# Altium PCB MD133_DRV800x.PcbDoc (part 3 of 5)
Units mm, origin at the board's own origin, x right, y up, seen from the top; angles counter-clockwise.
Board outline 152.66 x 101.89 mm, 4 copper layers (Top Layer, Mid-Layer 1, Mid-Layer 2, Bottom Layer), stack 2.355 mm thick; 306 components, 166 nets, 1010 pads, 1623 vias.
Unrouted connection lines stored in the file: 4.
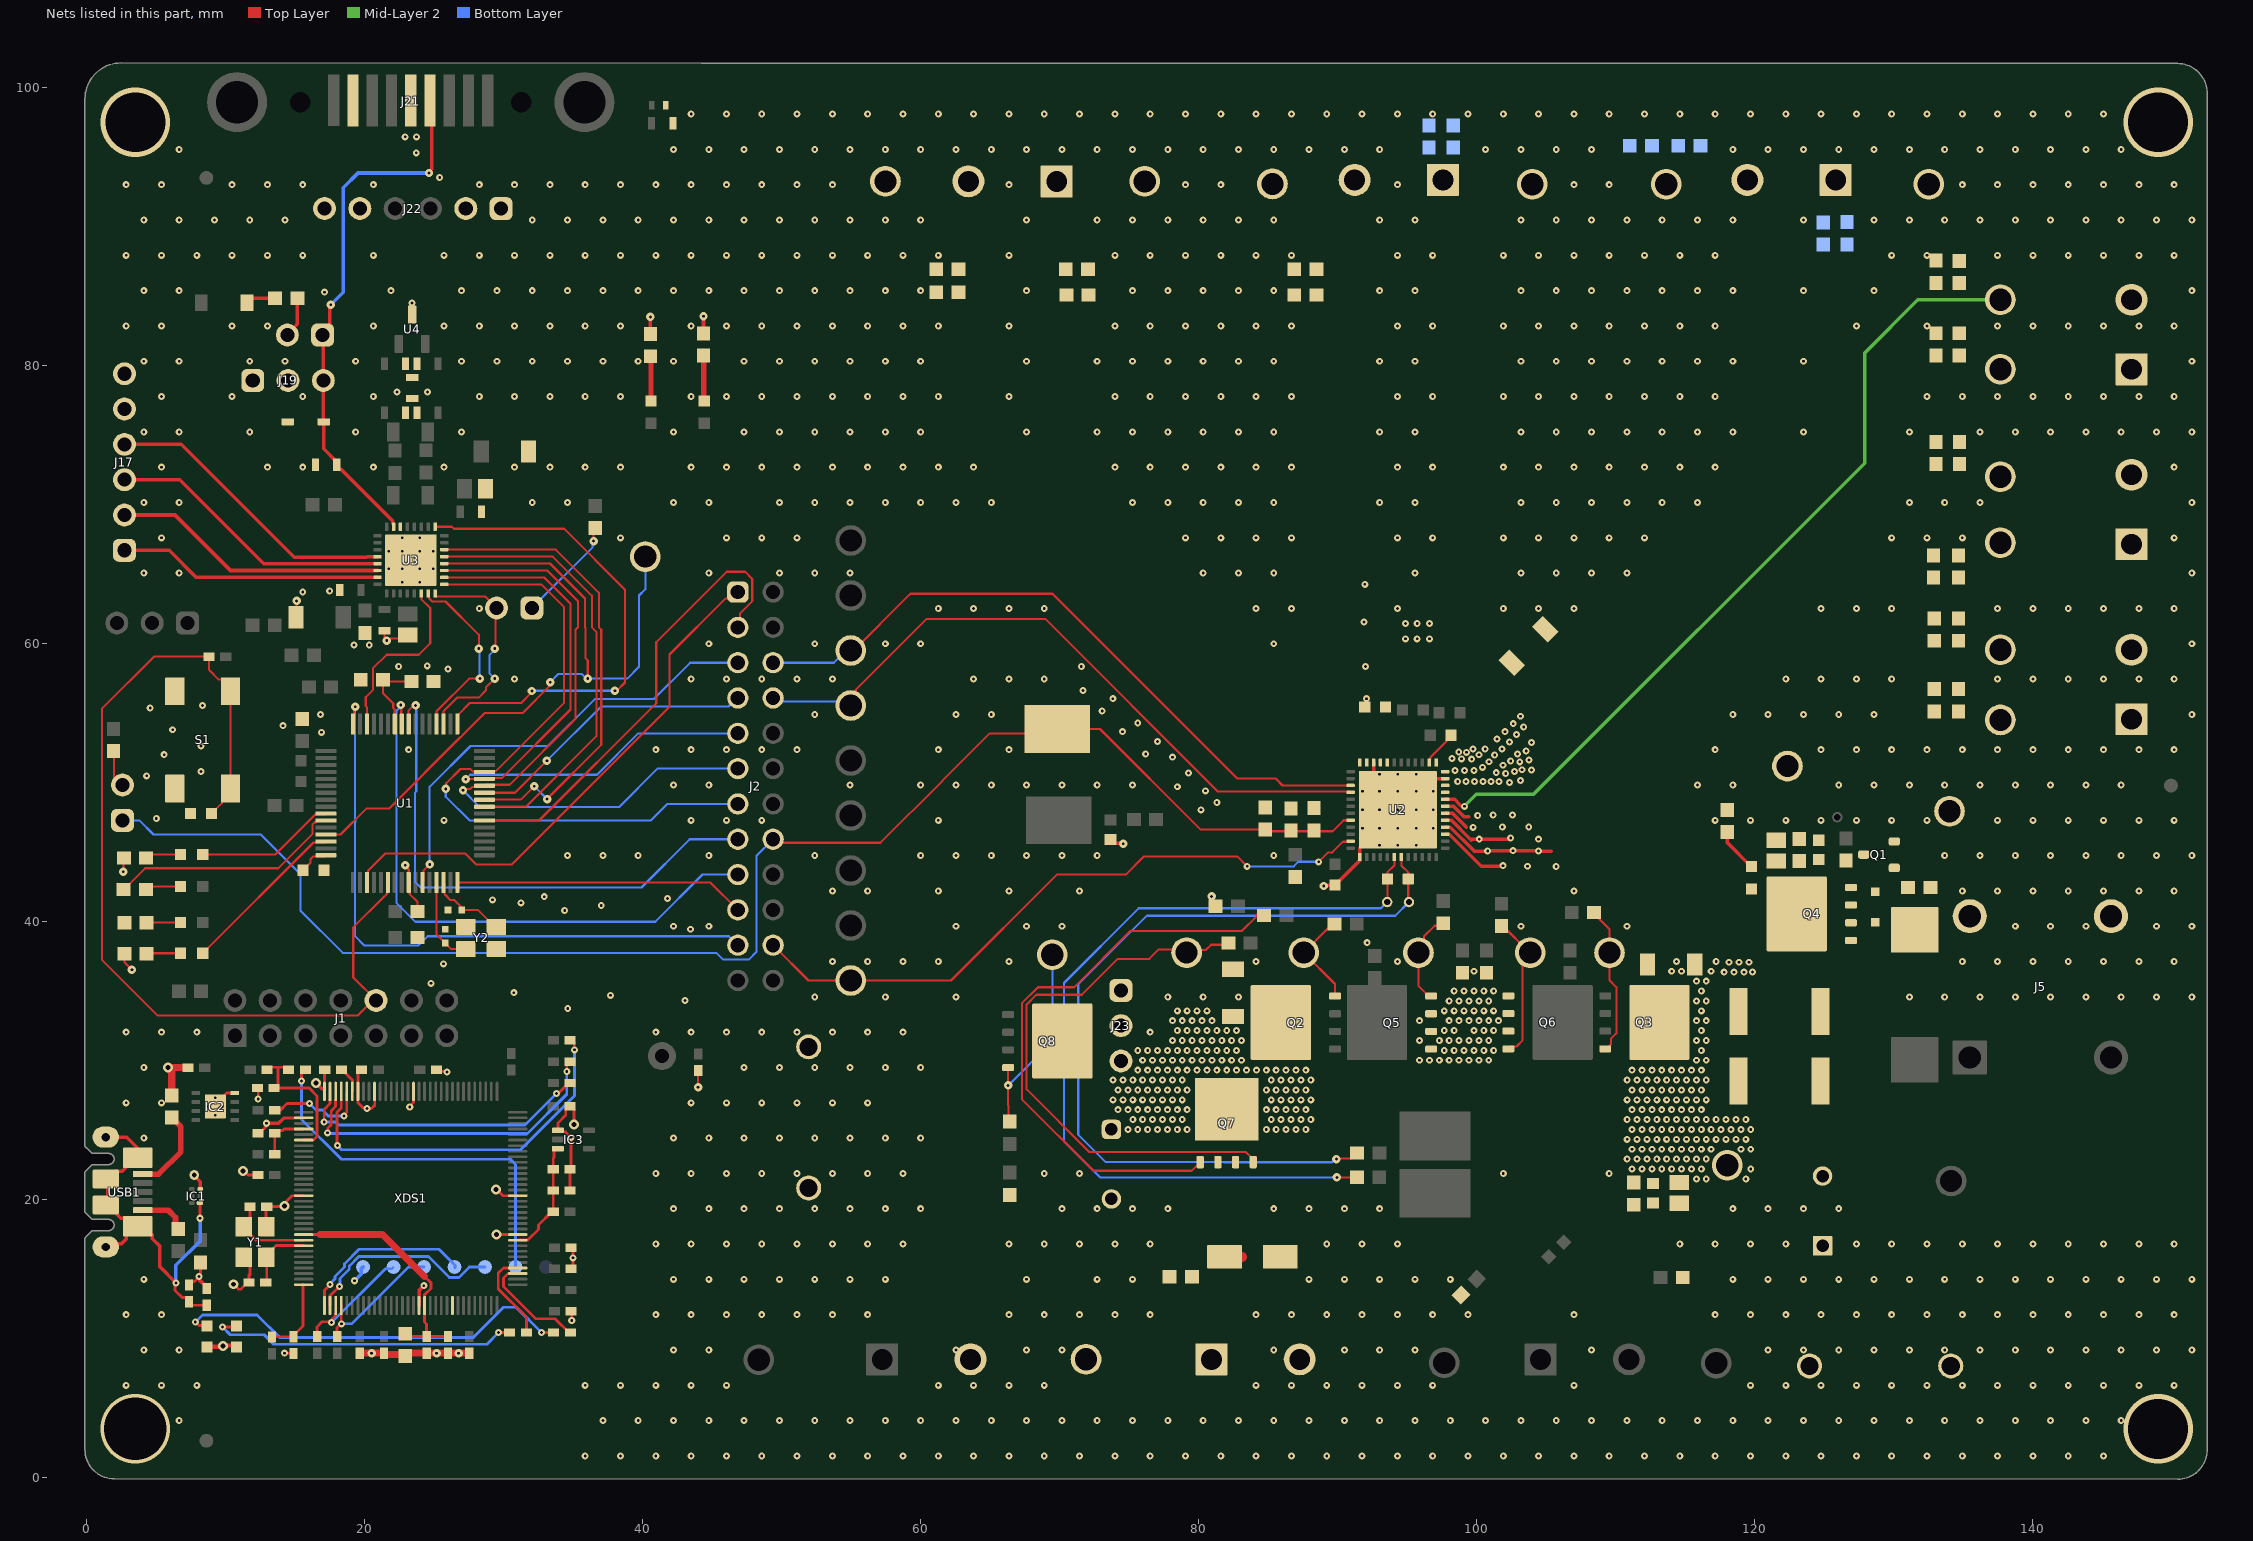
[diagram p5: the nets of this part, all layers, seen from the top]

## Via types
v1: diameter 0.5, hole 0.2, Top Layer to Bottom Layer, tented both sides, 1483 vias
v2: diameter 0.61, hole 0.2, Top Layer to Bottom Layer, tented both sides, 58 vias
v3: diameter 0.508, hole 0.203, Top Layer to Bottom Layer, tented both sides, 46 vias
v4: diameter 0.5, hole 0.2, Top Layer to Bottom Layer, 16 vias
v5: diameter 0.711, hole 0.356, Top Layer to Bottom Layer, tented both sides, 10 vias
v6: diameter 0.61, hole 0.203, Top Layer to Bottom Layer, tented both sides, 5 vias
v7: diameter 5, hole 4.3, Top Layer to Bottom Layer, 3 vias
v8: diameter 5, hole 4.5, Top Layer to Bottom Layer, 1 vias
v9: diameter 0.864, hole 0.406, Top Layer to Bottom Layer, tented both sides, 1 vias

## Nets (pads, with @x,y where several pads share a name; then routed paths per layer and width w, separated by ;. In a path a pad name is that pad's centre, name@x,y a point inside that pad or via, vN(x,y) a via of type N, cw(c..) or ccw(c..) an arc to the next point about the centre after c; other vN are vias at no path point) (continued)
GND: C1.2 C2.2 C3.2 C4.2 C5.2 C6.2 C7.2 C8.2 C9.2 C10.2 C11.2 C12.2 C13.2 C14.2 C15.2 C16.2 C17.2 C18.2 C19.2 C20.2 C21.2 C22.2 C23.2 C24.2 C25.1 C26.1 C28.1 C29.1 C30.1 C31.2 C32.1 C33.2 C34.2 C35.2 C36.2 C37.2 C38.2 C39.1 C41.1 C42.1 C43.1 C44.2 C45.1 C49.1 C50.1 C51.1 C52.1 C53.1 C54.1 C55.1 C56.1 C57.1 C58.1 C59.1 C60.1 C61.1 C63.2 C64.1 C65.1 C66.1 C67.2 C68.2 C69.2 C70.2 C71.1 C72.1 C73.1 C74.2 C75.2 C76.2 C77.2 C78.2 C79.2 C80.2 C81.2 C82.1 C83.2 C84.1 C85.2 C86.2 C87.1 C88.1 C89.1 C90.1 C91.1 C92.1 D9.2 D11.2 IC1.3 IC2.4 IC2.9 IC3.1 J5.2 J9.2 J16.2 J17.5 J17.6 J19.1 J19.2 J21.3 J21.6 J22.1 J22.2 J22.5 J22.6 LED1.2 LED2.2 Q5.1 Q5.2 Q5.3 Q6.1 Q6.2 Q6.3 R2.2 R3.1 R6.1 R15.1 R23.1 R27.1 R28.1 R29.1 R30.1 R33.1 R41.1 R42.1 R44.1 R57.1 R62.1 R63.1 R72.1 R77.1 S1.3 S1.4 SH1.1 SH1.2 SH2.1 SH2.2 TP1.1 TP25.1 TP26.1 U1.41 U2.10 U2.25 U2.47 U2.49 U3.30 U3.33 U4.3 XDS1.10 XDS1.17 XDS1.48 XDS1.55 XDS1.58 XDS1.64 XDS1.66 XDS1.80 XDS1.114 Y1.2 Y1.4 Y2.2 Y2.4 | length 94.7
  Top Layer w0.152: v2(2.634,43.577) 2.634,44.538 R29.1@2.677,44.582 ; R30.1@2.715,37.689 2.715,37.069 v2(3.25,36.534) ; C76.2@15.058,61.893 15.1,61.935 v2(15.1,63.066) ; C77.2@21.426,60.919 21.426,60.374 v2(21.59,60.21) 21.714,60.21 21.871,60.368 22.858,60.368 C75.2@23.108,60.618 ; v2(22.907,44.05) 22.907,44.004 23.162,43.749 U1.41@23.162,42.814 23.236,42.74 23.236,41.976 23.795,41.417 C24.2@23.795,40.714 ; U4.3@23.406,83.862 v1(23.406,84.497) ; C83.2@28.393,70.842 C83.2@28.681,71.131 C83.2@28.681,71.281 ; C78.2@31.304,73.086 31.778,73.559 C78.2@31.778,73.81 ; v2(43.979,28.086) R23.1@43.979,29.286 ; C45.1@91.938,55.421 92.052,55.535 v1(92.052,56.033) ; C45.1@91.988,55.421 C45.1@92.277,55.132
  Top Layer w0.203: R6.1@7.555,13.603 7.356,13.802 R6.1@7.356,13.848 R6.1@7.356,13.886 ; R6.1@7.645,14.146 7.555,14.146 7.356,13.948 R6.1@7.356,13.886 ; v3@8.027,14.529 8.182,14.683 C1.2@8.182,15.488 ; v3(8.089,14.467) 7.706,14.085 7.555,14.085 R6.1@7.356,13.886 ; v4(9.253,27.321) 9.753,27.321 9.902,27.469 9.902,27.524 10.048,27.671 IC2.4@10.653,27.671 ; v5(10.564,13.908) 10.572,13.908 10.924,13.556 11.093,13.556 11.578,14.042 C19.2@11.679,14.042 11.679,14.592 ; v5(11.242,22.062) 11.335,22.062 11.624,21.772 C5.2@12.329,21.772 ; Y1.4@11.395,16.19 11.395,15.801 11.753,15.443 11.753,14.592 ; C12.2@12.273,28.03 12.335,27.968 v3(12.335,27.243) ; C22.2@12.329,24.78 12.429,24.78 12.886,25.237 12.886,25.432 v3(12.944,25.491) v3@12.886,25.549 ; Y1.2@12.907,18.089 12.907,19.442 C18.2@12.953,19.488 12.974,19.509 14.203,19.509 v5(14.225,19.53) 14.322,19.627 14.322,19.832 14.77,20.28 XDS1.80@15.607,20.28 ; 14.163,25.872 14.172,25.88 XDS1.66@15.607,25.88 ; v3(14.225,8.949) 14.866,8.949 C11.2@14.88,8.935 ; XDS1.64@17.107,27.78 XDS1.64@17.107,27.978 ; XDS1.64@17.107,28.379 R15.1@17.107,29.323 ; C7.2@19.742,29.482 19.717,29.482 19.519,29.283 19.519,27.169 19.521,27.167 19.521,26.966 19.879,26.607 20.112,26.607 v3(20.17,26.549) 20.171,26.55 20.481,26.55 20.719,26.788 20.719,27.172 XDS1.55@20.709,27.182 ; v3(23.236,26.652) 23.236,26.707 23.507,26.978 XDS1.48@23.507,27.78 ; C6.2@25.157,29.336 25.261,29.232 25.865,29.232 v3(25.924,29.174) ; v5@29.48,17.489 XDS1.10@31.018,17.489 ; v5@29.51,20.715 29.945,20.28 XDS1.17@31.007,20.28 ; C20.2@34.756,20.651 C21.2@34.756,22.174 34.844,22.262 v3(34.844,24.479) 34.449,24.874 33.99,24.874 IC3.1@33.892,24.972 33.892,25.508 34.458,26.074 34.458,26.511 34.656,26.709 C14.2@34.756,26.709 34.844,26.709 35.042,26.511 v5(35.042,25.414) ; R3.1@34.844,11.976 34.89,11.931 v3(34.89,11.292) ; C8.2@34.844,15.022 34.991,15.17 v3(34.991,15.813) 34.991,16.398 C13.2@34.844,16.545
  Top Layer w0.254: v5(7.737,21.757) 7.737,21.72 8.164,21.293 IC1.3@8.164,20.758 ; v3(8.089,14.467) 8.118,14.438 8.118,14.212 8.626,13.703 C2.2@8.626,13.603 ; v3(12.944,25.491) 13.8,25.491 14.172,25.863 ; v5(16.5,28.386) 16.908,27.978 XDS1.64@17.08,27.978 ; XDS1.114@23.907,12.38 23.907,13.461 24.247,13.801 v3(24.247,13.807) ; v5(29.429,20.715) v5@29.51,20.715 ; v2(40.553,83.492) 40.553,82.273 R63.1@40.566,82.261 ; R62.1@44.368,82.311 v2(44.368,83.542) ; C63.2@73.636,45.9 73.909,45.627 74.536,45.627 v2(74.562,45.601) ; v2(88.978,42.557) 89.044,42.623 C43.1@89.798,42.623 91.563,44.388 91.563,44.637 U2.25@91.565,44.639 91.565,45.289 v1(94.315,48.039) ; U2.10@92.565,51.439 92.565,50.712 92.747,50.433 v1(94.315,48.039) ; U2.47@97.715,50.289 96.988,50.289 95.749,49.246 v1(94.315,48.039)
  Top Layer w0.305: LED1.2@8.753,9.349 8.81,9.406 9.738,9.406 v5(9.795,9.463) 9.838,9.506 10.742,9.506 LED2.2@10.785,9.549
  Top Layer w0.508: R2.2@6.117,27.496 6.117,29.189 5.858,29.449 v5(5.858,29.504) 5.869,29.493 7.278,29.493 C3.2@7.29,29.482 ; C9.2@19.637,8.949 v6(20.49,8.949) C10.2@21.387,8.949 21.387,8.895 21.433,8.849 22.82,8.849 C15.2@22.919,8.749 ; C15.2@22.919,8.949 C16.2@24.452,8.949 v6(25.168,8.949) C17.2@25.985,8.949 v6(26.749,8.949) C4.2@27.519,8.949
  Bottom Layer w0.254: v3(19.269,14.162) 19.736,14.629 19.736,15.01 TP1.1@19.878,15.153
  other v1: 35.86,1.563 38.4,1.563 40.94,1.563 43.48,1.563 46.02,1.563 48.56,1.563 51.1,1.563 53.64,1.563 56.18,1.563 58.72,1.563 61.26,1.563 63.8,1.563 66.34,1.563 68.88,1.563 71.42,1.563 73.96,1.563 76.5,1.563 79.04,1.563 81.58,1.563 84.12,1.563 86.66,1.563 89.2,1.563 91.74,1.563 94.28,1.563 96.82,1.563 99.36,1.563 101.9,1.563 104.44,1.563 106.98,1.563 109.52,1.563 112.06,1.563 114.6,1.563 117.14,1.563 119.68,1.563 122.22,1.563 124.76,1.563 127.3,1.563 129.84,1.563 132.38,1.563 134.92,1.563 137.46,1.563 140,1.563 142.54,1.563 145.08,1.563 6.65,4.103 37.13,4.103 39.67,4.103 42.21,4.103 44.75,4.103 47.29,4.103 49.83,4.103 52.37,4.103 54.91,4.103 57.45,4.103 59.99,4.103 62.53,4.103 65.07,4.103 67.61,4.103 70.15,4.103 72.69,4.103 75.23,4.103 77.77,4.103 80.31,4.103 82.85,4.103 85.39,4.103 87.93,4.103 90.47,4.103 93.01,4.103 95.55,4.103 98.09,4.103 100.63,4.103 103.17,4.103 105.71,4.103 108.25,4.103 110.79,4.103 113.33,4.103 115.87,4.103 118.41,4.103 120.95,4.103 123.49,4.103 126.03,4.103 128.57,4.103 131.11,4.103 133.65,4.103 136.19,4.103 138.73,4.103 141.27,4.103 143.81,4.103 146.35,4.103 2.84,6.643 5.38,6.643 7.92,6.643 35.86,6.643 38.4,6.643 40.94,6.643 43.48,6.643 46.02,6.643 61.26,6.643 63.8,6.643 66.34,6.643 68.88,6.643 84.12,6.643 86.66,6.643 89.2,6.643 91.74,6.643 94.28,6.643 96.82,6.643 106.98,6.643 119.68,6.643 122.22,6.643 124.76,6.643 127.3,6.643 129.84,6.643 132.38,6.643 134.92,6.643 137.46,6.643 140,6.643 142.54,6.643 145.08,6.643 147.62,6.643 150.16,6.643 4.11,9.183 6.65,9.183 42.21,9.183 44.75,9.183 62.53,9.183 67.61,9.183 70.15,9.183 85.39,9.183 90.47,9.183 93.01,9.183 95.55,9.183 108.25,9.183 120.95,9.183 123.49,9.183 126.03,9.183 128.57,9.183 131.11,9.183 133.65,9.183 136.19,9.183 138.73,9.183 141.27,9.183 143.81,9.183 146.35,9.183 148.89,9.183 151.43,9.183 2.84,11.723 5.38,11.723 40.94,11.723 43.48,11.723 46.02,11.723 48.56,11.723 51.1,11.723 53.64,11.723 56.18,11.723 66.34,11.723 68.88,11.723 71.42,11.723 73.96,11.723 76.5,11.723 84.12,11.723 86.66,11.723 89.2,11.723 91.74,11.723 94.28,11.723 96.82,11.723 99.36,11.723 106.98,11.723 117.14,11.723 119.68,11.723 122.22,11.723 124.76,11.723 127.3,11.723 129.84,11.723 132.38,11.723 134.92,11.723 137.46,11.723 140,11.723 142.54,11.723 145.08,11.723 147.62,11.723 150.16,11.723 4.11,14.263 42.21,14.263 44.75,14.263 47.29,14.263 49.83,14.263 52.37,14.263 54.91,14.263 57.45,14.263 67.61,14.263 72.69,14.263 75.23,14.263 87.93,14.263 90.47,14.263 93.01,14.263 95.55,14.263 98.09,14.263 118.41,14.263 120.95,14.263 123.49,14.263 126.03,14.263 128.57,14.263 131.11,14.263 133.65,14.263 136.19,14.263 138.73,14.263 141.27,14.263 143.81,14.263 146.35,14.263 148.89,14.263 151.43,14.263 40.94,16.803 43.48,16.803 46.02,16.803 48.56,16.803 51.1,16.803 53.64,16.803 56.18,16.803 58.72,16.803 66.34,16.803 68.88,16.803 71.42,16.803 73.96,16.803 76.5,16.803 89.2,16.803 91.74,16.803 94.28,16.803 114.6,16.803 117.14,16.803 119.68,16.803 122.22,16.803 127.3,16.803 129.84,16.803 132.38,16.803 134.92,16.803 137.46,16.803 140,16.803 142.54,16.803 145.08,16.803 147.62,16.803 150.16,16.803 42.21,19.343 44.75,19.343 47.29,19.343 49.83,19.343 52.37,19.343 54.91,19.343 57.45,19.343 59.99,19.343 70.15,19.343 72.69,19.343 75.23,19.343 77.77,19.343 85.39,19.343 87.93,19.343 90.47,19.343 93.01,19.343 118.41,19.343 120.95,19.343 123.49,19.343 126.03,19.343 40.94,21.883 43.48,21.883 46.02,21.883 48.56,21.883 51.1,21.883 53.64,21.883 56.18,21.883 58.72,21.883 68.88,21.883 71.42,21.883 101.9,21.883 109.52,21.883 4.11,24.423 42.21,24.423 44.75,24.423 47.29,24.423 49.83,24.423 52.37,24.423 54.91,24.423 57.45,24.423 59.99,24.423 2.84,26.963 5.38,26.963 43.48,26.963 46.02,26.963 48.56,26.963 51.1,26.963 53.64,26.963 56.18,26.963 4.11,29.503 47.29,29.503 49.83,29.503 52.37,29.503 54.91,29.503 57.45,29.503 59.99,29.503 95.875,30.023 96.586,30.023 97.298,30.023 98.009,30.023 98.72,30.023 99.431,30.023 100.142,30.023 100.854,30.023 97.653,30.734 98.364,30.734 99.076,30.734 99.787,30.734 100.498,30.734 101.209,30.734 95.875,31.445 97.298,31.445 98.009,31.445 98.72,31.445 99.431,31.445 100.142,31.445 100.854,31.445 2.84,32.043 5.38,32.043 7.92,32.043 40.94,32.043 43.48,32.043 46.02,32.043 48.56,32.043 51.1,32.043 53.64,32.043 56.18,32.043 58.72,32.043 76.5,32.043 97.653,32.156 98.364,32.156 99.787,32.156 100.498,32.156 101.209,32.156 95.875,32.868 98.009,32.868 98.72,32.868 99.431,32.868 100.142,32.868 100.854,32.868 101.565,32.868 97.653,33.579 98.364,33.579 99.076,33.579 99.787,33.579 100.498,33.579 101.209,33.579 34.605,33.739 98.009,34.29 98.72,34.29 99.431,34.29 100.142,34.29 100.854,34.29 43.043,34.321 52.37,34.583 57.45,34.583 62.53,34.583 77.77,34.583 80.31,34.583 82.85,34.583 131.11,34.583 133.65,34.583 136.19,34.583 138.73,34.583 141.27,34.583 143.81,34.583 146.35,34.583 148.89,34.583 151.43,34.583 37.677,34.696 30.725,34.881 98.364,35.001 99.076,35.001 99.787,35.001 100.498,35.001 101.209,35.001 24.763,35.56 99.787,36.424 25.662,36.96 53.64,37.123 56.18,37.123 58.72,37.123 61.26,37.123 66.34,37.123 84.12,37.123 94.28,37.123 134.92,37.123 137.46,37.123 140,37.123 142.54,37.123 145.08,37.123 147.62,37.123 150.16,37.123 92.11,38.483 43.425,39.448 42.21,39.663 44.75,39.663 62.53,39.663 67.61,39.663 70.15,39.663 103.17,39.663 110.79,39.663 138.73,39.663 141.27,39.663 143.81,39.663 148.89,39.663 151.43,39.663 34.385,40.804 37.013,41.152 31.248,41.35 29.195,41.567 41.773,41.656 32.913,41.79 53.64,42.203 56.18,42.203 61.26,42.203 66.34,42.203 71.42,42.203 106.98,42.203 134.92,42.203 137.46,42.203 140,42.203 142.54,42.203 145.08,42.203 147.62,42.203 150.16,42.203 34.59,44.743 37.13,44.743 39.67,44.743 44.75,44.743 52.37,44.743 59.99,44.743 62.53,44.743 65.07,44.743 67.61,44.743 70.15,44.743 72.69,44.743 85.39,44.743 133.65,44.743 136.19,44.743 138.73,44.743 141.27,44.743 143.81,44.743 146.35,44.743 148.89,44.743 151.43,44.743 92.985,45.489 94.315,45.489 95.645,45.489 91.765,46.709 92.985,46.709 94.315,46.709 95.645,46.709 96.865,46.709 25.7,47.283 43.48,47.283 46.02,47.283 48.56,47.283 61.26,47.283 117.14,47.283 119.68,47.283 122.22,47.283 124.76,47.283 127.3,47.283 129.84,47.283 132.38,47.283 137.46,47.283 140,47.283 142.54,47.283 145.08,47.283 147.62,47.283 150.16,47.283 5.005,47.413 80.159,48.039 91.765,48.039 92.985,48.039 95.645,48.039 96.865,48.039 81.296,48.573 91.765,49.369 92.985,49.369 94.315,49.369 95.645,49.369 96.865,49.369 80.478,49.402 78.451,49.698 42.21,49.823 44.75,49.823 54.91,49.823 59.99,49.823 62.53,49.823 65.07,49.823 67.61,49.823 70.15,49.823 72.69,49.823 75.23,49.823 115.87,49.823 118.41,49.823 126.03,49.823 128.57,49.823 131.11,49.823 133.65,49.823 136.19,49.823 138.73,49.823 141.27,49.823 143.81,49.823 146.35,49.823 4.315,50.482 92.985,50.589 94.315,50.589 95.645,50.589 79.266,50.677 8.218,50.8 78.095,51.827 5.573,52.002 76.173,52.044 23.16,52.363 40.94,52.363 43.48,52.363 46.02,52.363 48.56,52.363 51.1,52.363 61.26,52.363 66.34,52.363 117.14,52.363 124.76,52.363 127.3,52.363 129.84,52.363 132.38,52.363 134.92,52.363 137.46,52.363 140,52.363 142.54,52.363 145.08,52.363 147.62,52.363 150.16,52.363 8.218,52.628 77.028,52.944 16.895,53.614 74.51,53.655 6.187,53.796 14.121,54.089 75.606,54.275 16.81,54.903 52.37,54.903 62.53,54.903 65.07,54.903 118.41,54.903 120.95,54.903 123.49,54.903 126.03,54.903 128.57,54.903 151.43,54.903 73.048,55.145 4.567,55.356 8.326,55.551 73.81,56.033 71.66,56.629 30.78,57.443 43.48,57.443 46.02,57.443 48.56,57.443 51.1,57.443 53.64,57.443 63.8,57.443 66.34,57.443 68.88,57.443 122.22,57.443 124.76,57.443 127.3,57.443 129.84,57.443 137.46,57.443 140,57.443 142.54,57.443 145.08,57.443 147.62,57.443 150.16,57.443 25.984,58.162 22.443,58.339 71.543,58.353 91.99,58.353 24.495,58.395 44.75,59.983 52.37,59.983 57.45,59.983 59.99,59.983 85.39,59.983 151.43,59.983 91.888,61.543 28.24,62.523 61.26,62.523 63.8,62.523 66.34,62.523 68.88,62.523 84.12,62.523 86.66,62.523 94.28,62.523 101.9,62.523 104.44,62.523 106.98,62.523 124.76,62.523 127.3,62.523 129.84,62.523 137.46,62.523 140,62.523 142.54,62.523 145.08,62.523 147.62,62.523 150.16,62.523 15.542,63.714 17.48,63.772 91.938,64.26 4.11,65.063 6.65,65.063 44.75,65.063 49.83,65.063 52.37,65.063 54.91,65.063 80.31,65.063 82.85,65.063 85.39,65.063 95.55,65.063 103.17,65.063 105.71,65.063 108.25,65.063 110.79,65.063 151.43,65.063 5.38,67.603 38.4,67.603 46.02,67.603 48.56,67.603 51.1,67.603 79.04,67.603 81.58,67.603 84.12,67.603 86.66,67.603 94.28,67.603 96.82,67.603 101.9,67.603 104.44,67.603 106.98,67.603 109.52,67.603 112.06,67.603 129.84,67.603 132.38,67.603 134.92,67.603 150.16,67.603 4.11,70.143 6.65,70.143 32.05,70.143 34.59,70.143 42.21,70.143 44.75,70.143 49.83,70.143 52.37,70.143 54.91,70.143 57.45,70.143 59.99,70.143 62.53,70.143 65.07,70.143 75.23,70.143 77.77,70.143 80.31,70.143 82.85,70.143 85.39,70.143 93.01,70.143 95.55,70.143 103.17,70.143 105.71,70.143 108.25,70.143 110.79,70.143 113.33,70.143 115.87,70.143 131.11,70.143 133.65,70.143 136.19,70.143 151.43,70.143 5.38,72.683 13,72.683 15.54,72.683 20.62,72.683 25.7,72.683 30.78,72.683 33.32,72.683 35.86,72.683 38.4,72.683 43.48,72.683 46.02,72.683 48.56,72.683 51.1,72.683 53.64,72.683 56.18,72.683 58.72,72.683 61.26,72.683 63.8,72.683 73.96,72.683 76.5,72.683 79.04,72.683 81.58,72.683 84.12,72.683 86.66,72.683 94.28,72.683 96.82,72.683 101.9,72.683 104.44,72.683 106.98,72.683 109.52,72.683 112.06,72.683 114.6,72.683 117.14,72.683 150.16,72.683 4.11,75.223 6.65,75.223 11.73,75.223 19.35,75.223 26.97,75.223 42.21,75.223 47.29,75.223 49.83,75.223 52.37,75.223 54.91,75.223 57.45,75.223 59.99,75.223 67.61,75.223 72.69,75.223 75.23,75.223 77.77,75.223 80.31,75.223 82.85,75.223 85.39,75.223 93.01,75.223 95.55,75.223 103.17,75.223 105.71,75.223 108.25,75.223 110.79,75.223 113.33,75.223 115.87,75.223 118.41,75.223 123.49,75.223 131.11,75.223 136.19,75.223 138.73,75.223 141.27,75.223 143.81,75.223 146.35,75.223 148.89,75.223 151.43,75.223 5.38,77.763 10.46,77.763 15.54,77.763 20.62,77.763 28.24,77.763 30.78,77.763 33.32,77.763 35.86,77.763 38.4,77.763 43.48,77.763 46.02,77.763 48.56,77.763 51.1,77.763 53.64,77.763 56.18,77.763 58.72,77.763 61.26,77.763 66.34,77.763 73.96,77.763 76.5,77.763 79.04,77.763 81.58,77.763 84.12,77.763 86.66,77.763 94.28,77.763 96.82,77.763 101.9,77.763 104.44,77.763 106.98,77.763 109.52,77.763 112.06,77.763 114.6,77.763 117.14,77.763 132.38,77.763 134.92,77.763 137.46,77.763 140,77.763 142.54,77.763 145.08,77.763 147.62,77.763 150.16,77.763 22.32,78.101 24.519,78.101 4.11,80.303 6.65,80.303 11.73,80.303 14.27,80.303 19.35,80.303 26.97,80.303 29.51,80.303 32.05,80.303 34.59,80.303 37.13,80.303 39.67,80.303 42.21,80.303 47.29,80.303 49.83,80.303 52.37,80.303 54.91,80.303 57.45,80.303 59.99,80.303 67.61,80.303 72.69,80.303 75.23,80.303 77.77,80.303 80.31,80.303 82.85,80.303 85.39,80.303 93.01,80.303 95.55,80.303 103.17,80.303 105.71,80.303 108.25,80.303 110.79,80.303 113.33,80.303 115.87,80.303 118.41,80.303 123.49,80.303 151.43,80.303 2.84,82.843 5.38,82.843 10.46,82.843 13,82.843 20.62,82.843 25.7,82.843 28.24,82.843 30.78,82.843 33.32,82.843 35.86,82.843 38.4,82.843 43.48,82.843 46.02,82.843 48.56,82.843 51.1,82.843 53.64,82.843 56.18,82.843 58.72,82.843 61.26,82.843 66.34,82.843 73.96,82.843 76.5,82.843 79.04,82.843 81.58,82.843 84.12,82.843 86.66,82.843 94.28,82.843 96.82,82.843 101.9,82.843 104.44,82.843 106.98,82.843 109.52,82.843 112.06,82.843 114.6,82.843 117.14,82.843 127.3,82.843 132.38,82.843 137.46,82.843 140,82.843 142.54,82.843 145.08,82.843 147.62,82.843 150.16,82.843 17.109,85.273 4.11,85.383 6.65,85.383 21.89,85.383 26.97,85.383 29.51,85.383 32.05,85.383 34.59,85.383 37.13,85.383 39.67,85.383 42.21,85.383 44.75,85.383 47.29,85.383 49.83,85.383 52.37,85.383 54.91,85.383 57.45,85.383 59.99,85.383 67.61,85.383 75.23,85.383 77.77,85.383 80.31,85.383 82.85,85.383 85.39,85.383 93.01,85.383 95.55,85.383 103.17,85.383 105.71,85.383 108.25,85.383 110.79,85.383 113.33,85.383 115.87,85.383 118.41,85.383 123.49,85.383 128.57,85.383 151.43,85.383 2.84,87.923 5.38,87.923 7.92,87.923 10.46,87.923 13,87.923 15.54,87.923 20.62,87.923 25.7,87.923 28.24,87.923 30.78,87.923 33.32,87.923 35.86,87.923 38.4,87.923 40.94,87.923 43.48,87.923 46.02,87.923 48.56,87.923 51.1,87.923 53.64,87.923 56.18,87.923 58.72,87.923 61.26,87.923 66.34,87.923 73.96,87.923 76.5,87.923 79.04,87.923 81.58,87.923 84.12,87.923 86.66,87.923 94.28,87.923 96.82,87.923 101.9,87.923 104.44,87.923 106.98,87.923 109.52,87.923 112.06,87.923 114.6,87.923 117.14,87.923 129.84,87.923 132.38,87.923 137.46,87.923 140,87.923 142.54,87.923 145.08,87.923 147.62,87.923 150.16,87.923 4.11,90.463 6.65,90.463 9.19,90.463 11.73,90.463 14.27,90.463 32.05,90.463 34.59,90.463 37.13,90.463 39.67,90.463 42.21,90.463 44.75,90.463 47.29,90.463 49.83,90.463 52.37,90.463 54.91,90.463 57.45,90.463 59.99,90.463 67.61,90.463 72.69,90.463 75.23,90.463 77.77,90.463 80.31,90.463 82.85,90.463 85.39,90.463 93.01,90.463 95.55,90.463 103.17,90.463 105.71,90.463 108.25,90.463 110.79,90.463 113.33,90.463 115.87,90.463 118.41,90.463 123.49,90.463 128.57,90.463 131.11,90.463 133.65,90.463 136.19,90.463 138.73,90.463 141.27,90.463 143.81,90.463 146.35,90.463 148.89,90.463 151.43,90.463 2.84,93.003 5.38,93.003 10.46,93.003 13,93.003 15.54,93.003 20.62,93.003 28.24,93.003 30.78,93.003 33.32,93.003 35.86,93.003 38.4,93.003 40.94,93.003 43.48,93.003 46.02,93.003 48.56,93.003 51.1,93.003 53.64,93.003 66.34,93.003 79.04,93.003 81.58,93.003 94.28,93.003 106.98,93.003 109.52,93.003 134.92,93.003 137.46,93.003 140,93.003 142.54,93.003 145.08,93.003 147.62,93.003 150.16,93.003 25.392,93.529 23.704,95.301 6.65,95.543 42.21,95.543 44.75,95.543 47.29,95.543 49.83,95.543 52.37,95.543 54.91,95.543 57.45,95.543 59.99,95.543 62.53,95.543 65.07,95.543 67.61,95.543 70.15,95.543 72.69,95.543 75.23,95.543 77.77,95.543 80.31,95.543 82.85,95.543 85.39,95.543 87.93,95.543 90.47,95.543 93.01,95.543 100.63,95.543 103.17,95.543 105.71,95.543 108.25,95.543 118.41,95.543 120.95,95.543 123.49,95.543 126.03,95.543 128.57,95.543 131.11,95.543 133.65,95.543 136.19,95.543 138.73,95.543 141.27,95.543 143.81,95.543 146.35,95.543 22.906,96.45 23.724,96.45 43.48,98.083 46.02,98.083 48.56,98.083 51.1,98.083 53.64,98.083 56.18,98.083 58.72,98.083 61.26,98.083 63.8,98.083 66.34,98.083 68.88,98.083 71.42,98.083 73.96,98.083 76.5,98.083 79.04,98.083 81.58,98.083 84.12,98.083 86.66,98.083 89.2,98.083 91.74,98.083 94.28,98.083 96.82,98.083 99.36,98.083 101.9,98.083 104.44,98.083 106.98,98.083 109.52,98.083 112.06,98.083 114.6,98.083 117.14,98.083 119.68,98.083 122.22,98.083 124.76,98.083 127.3,98.083 129.84,98.083 132.38,98.083 134.92,98.083 137.46,98.083 140,98.083 142.54,98.083 145.08,98.083
  other v2: 80.915,41.808
  other v4: 9.253,26.071 8.753,26.696 9.753,26.696 22.69,64.403 23.95,64.403 21.72,65.373 22.69,65.373 23.95,65.373 24.92,65.373 21.72,66.633 22.69,66.633 23.95,66.633 24.92,66.633 22.69,67.603 23.95,67.603
  other v5: 29.48,17.49
  other v7: 149,3.5 3.5,97.5 149,97.5
  other v8: 3.5,3.5
GUI_STATUS: D3.2 U1.30 | length 12.2
  Top Layer w0.152: D3.2@8.345,37.724 16.312,45.69 17.138,45.69 U1.30@17.212,45.764
HFXIN: C29.2 U1.45 Y2.3 | length 6.3
  Top Layer w0.152: U1.45@25.162,42.814 25.162,39.078 C29.2@25.793,38.448 26.222,38.018 Y2.3@27.272,38.018
HFXOUT: C28.2 U1.46 Y2.1 | length 5.6
  Top Layer w0.152: U1.46@25.662,42.814 25.736,42.74 25.736,41.979 26.171,41.543 26.461,41.543 27.164,40.841 28.124,40.841 29.347,39.618 Y2.1@29.472,39.618
HSS1: J17.1 U3.7 | length 19
  Top Layer w0.254: J17.1@2.715,66.706 5.927,66.706 7.88,64.753 U3.7@20.92,64.753
HSS2: J17.2 U3.6 | length 19.9
  Top Layer w0.254: J17.2@2.715,69.246 6.351,69.246 10.344,65.253 U3.6@20.92,65.253
HSS3: J17.3 U3.5 | length 20.7
  Top Layer w0.254: J17.3@2.715,71.786 6.698,71.786 12.736,65.748 20.307,65.748 20.311,65.753 U3.5@20.92,65.753
HSS4: J17.4 U3.4 | length 21.6
  Top Layer w0.254: J17.4@2.715,74.326 6.812,74.326 14.936,66.202 20.119,66.202 20.169,66.253 U3.4@20.92,66.253
IPROPI/PWM2: C67.1 C68.1 J2.16 J3.1 R57.2 TP16.1 U2.20 | length 110.8
  Top Layer w0.152: J2.16@49.378,45.921 49.632,45.667 57.093,45.667 61.567,50.141 61.567,50.154 61.875,50.463 64.953,53.541 TP16.1@72.107,53.541 ; TP16.1@69.811,53.849 72.895,53.849 80.135,46.609 C68.1@84.771,46.609 84.886,46.494 R57.2@86.63,46.494 ; R57.2@86.63,46.594 R57.2@86.63,46.494 ; U2.20@90.915,47.289 90.416,47.289 89.621,46.494 R57.2@86.63,46.494
  Bottom Layer w0.152: J3.1@2.573,47.28 3.788,47.28 4.804,46.264 12.529,46.264 15.368,43.425 15.368,40.796 18.416,37.748 45.295,37.748 45.784,37.259 47.625,37.259 48.172,37.807 48.172,44.715 J2.16@49.378,45.921
IRSTN: R16.1 TP6.1 | length 27.8
  Top Layer w0.203: v3(15.459,28.539) 15.459,29.148 R16.1@15.662,29.351
  Bottom Layer w0.203: v3(15.459,28.539) 15.459,25.763 18.322,22.9 30.47,22.9 30.843,22.527 TP6.1@30.843,15.153
ITCK: R8.2 TP3.1 XDS1.100 | length 10
  Top Layer w0.203: R8.2@18.011,10.149 18.011,10.804 18.271,11.063 v3(18.329,11.063) 18.307,11.085 XDS1.100@18.307,12.38
  Bottom Layer w0.203: v3(18.329,11.063) 19.048,11.063 23.138,15.153 TP3.1@24.264,15.153 TP3.1@24.273,15.153
ITDI: TP5.1 XDS1.98 | length 14.4
  Top Layer w0.203: XDS1.98@17.507,12.38 17.507,13.081 18.177,13.75 v3(18.177,13.756)
  Bottom Layer w0.203: v3(18.177,13.756) 18.215,13.795 18.215,14.332 18.891,15.007 18.891,15.232 19.566,15.907 21.501,15.907 24.576,15.907 26.084,14.399 26.769,14.399 27.523,15.153 TP5.1@28.65,15.153
ITDO: TP4.1 XDS1.97 | length 12
  Top Layer w0.203: XDS1.97@17.107,12.979 17.107,13.476 17.491,13.859 v3(17.491,13.883)
  Bottom Layer w0.203: v3(17.491,13.883) 17.491,13.935 17.86,14.304 17.86,14.479 18.535,15.154 18.535,15.379 19.579,16.423 25.339,16.423 26.482,15.28 TP4.1@26.482,15.102
ITMS: R7.2 TP2.1 XDS1.99 | length 8.7
  Top Layer w0.203: R7.2@16.567,10.135 16.567,10.84 16.935,11.208 17.575,11.208 v3(17.618,11.165) 17.676,11.223 17.676,11.434 17.906,11.663 XDS1.99@17.906,11.782
  Bottom Layer w0.203: v3(17.618,11.165) 21.473,15.02 21.93,15.02 TP2.1@22.024,15.114
LIN_PU: D8.1 R65.1 | length 2.2
  Top Layer w0.254: D8.1@11.523,84.513 11.853,84.843 R65.1@13.553,84.843
LIN_PU_EN: J18.2 R65.2 | length 3.3
  Top Layer w0.254: J18.2@14.432,82.192 14.432,82.245 15.153,82.966 R65.2@15.153,85.103 ; R65.2@14.861,84.843 R65.2@14.925,84.779
MCU_CAN_GFO: U1.1 U3.25 | length 35.9
  Top Layer w0.152: U3.25@25.07,68.403 26.267,68.403 26.417,68.253 34.341,68.253 38.719,63.875 38.719,57.2 38.118,56.599 v2(37.994,56.599) ; U1.1@26.662,54.214 26.662,54.814 27.566,55.718 31.248,55.718 32.026,56.496 v2(32.026,56.585)
  Bottom Layer w0.152: v2(32.026,56.585) 32.04,56.599 v2(37.994,56.599)
MCU_CAN_LRXD: U1.57 U3.22 | length 34.2
  Top Layer w0.152: U3.22@25.72,66.753 33.741,66.753 36.841,63.653 36.841,61.161 37.013,60.988 37.013,52.712 v2(33.115,48.813) ; U1.57@28.612,48.764 28.637,48.789 31.251,48.789 v2(32.201,49.739)
  Bottom Layer w0.152: v2(32.201,49.739) 32.201,49.727 v2(33.115,48.813)
MCU_CAN_LTXD: U1.56 U3.21 | length 32.2
  Top Layer w0.152: U3.21@25.72,66.253 33.534,66.253 36.341,63.446 36.341,61.161 36.661,60.84 36.661,53.327 31.598,48.264 U1.56@28.612,48.264
MCU_CAN_nINT: U1.4 U3.15 | length 13.2
  Top Layer w0.152: U3.15@24.57,63.603 24.619,63.554 24.619,63.268 24.86,63.027 25.809,63.027 28.208,60.628 v2(28.208,59.636) ; U1.4@25.162,54.214 25.162,55.119 27.521,57.477 v2(28.285,57.477)
  Bottom Layer w0.152: v2(28.208,59.636) 28.246,59.598 28.246,57.516 v2(28.285,57.477)
MCU_CAN_nRST: U1.14 U3.14 | length 13
  Top Layer w0.152: U1.14@20.162,54.214 20.162,55.409 20.074,55.497 20.074,56.138 20.587,56.65 20.587,58.211 21.571,59.195 23.897,59.195 24.713,60.01 24.713,60.581 24.713,62.555 24.075,63.193 24.075,63.598 U3.14@24.07,63.603
MCU_CAN_SW: J20.2 U1.3 U3.16 | length 16.2
  Top Layer w0.152: U3.16@25.07,63.603 25.07,63.379 28.662,63.379 29.397,62.644 29.397,59.688 v2(29.345,59.636) ; U1.3@25.662,54.214 25.662,55.134 26.632,56.104 28.194,56.104 28.722,56.632 28.722,56.854 v2(29.345,57.477)
  Bottom Layer w0.152: v2@29.258,57.39 v2(29.345,57.477) 28.968,57.854 28.968,59.151 29.345,59.529 v2(29.345,59.636)
MCU_DRVOFF: J2.19 U1.48 | length 21
  Top Layer w0.152: U1.48@26.662,42.814 44.864,42.814 J2.19@46.838,40.841
MCU_GD_IN1: J2.1 U1.35 | length 38.6
  Top Layer w0.152: U1.35@20.162,42.814 20.236,42.888 20.236,43.577 20.236,43.649 21.483,44.896 27.219,44.896 28.003,44.112 30.596,44.112 41.924,55.44 41.924,59.21 45.964,63.25 46.387,63.25 J2.1@46.838,63.701
MCU_GD_IN2: J2.3 U1.54 | length 33.4
  Top Layer w0.152: U1.54@28.612,47.264 32.538,47.264 40.97,55.696 40.97,60.089 46.042,65.161 47.361,65.161 47.879,64.643 47.879,63.045 46.988,62.154 46.988,61.311 J2.3@46.838,61.161
MCU_IPROPI/PWM2: J2.15 U1.8 | length 39.2
  Top Layer w0.152: U1.8@23.162,54.214 23.155,54.221 23.155,55.193 23.422,55.46 23.565,55.46 v2(23.652,55.547)
  Bottom Layer w0.152: v2(23.652,55.547) 23.706,55.494 23.706,49.369 23.608,49.271 23.608,42.868 24.028,42.448 39.908,42.448 43.381,45.921 J2.15@46.838,45.921
MCU_nSCS_CAN: TP49.1 U1.29 U3.20 | length 53
  Top Layer w0.152: U1.29@17.212,46.264 18.26,46.264 20.12,48.124 21.741,48.124 26.852,53.235 26.878,53.235 27.041,53.398 27.041,53.424 28.62,55.003 31.355,55.003 33.345,56.993 v2@33.345,57.103 ; U3.20@25.72,65.753 33.327,65.753 35.841,63.239 35.841,61.161 35.892,61.11 35.892,58.937 36.04,58.789 v2(36.04,57.477)
  Bottom Layer w0.152: v2@33.345,57.103 v2(33.345,57.218) 33.929,57.802 35.611,57.802 35.936,57.477 v2(36.04,57.477) 38.878,57.477 39.732,58.332 39.732,63.451 40.185,63.904 TP49.1@40.185,66.253
MCU_nSCS_DRV: J2.7 U1.58 | length 21
  Top Layer w0.152: U1.58@28.612,49.264 30.804,49.264 v2(33.104,51.564)
  Bottom Layer w0.152: v2(33.104,51.564) 37.012,55.472 46.168,55.472 46.776,56.081 J2.7@46.838,56.081
MCU_nSLEEP: J2.21 U1.16 | length 46.2
  Top Layer w0.152: U1.16@19.162,54.214 19.236,54.288 19.236,55.382 v2(19.311,55.457)
  Bottom Layer w0.152: v2(19.311,55.457) 19.311,47.443 cw(c18.626,47.264) 19.311,47.085 19.311,38.947 19.977,38.281 23.857,38.281 24.523,38.947 46.191,38.947 J2.21@46.838,38.301
MCU_PWM1: J2.5 U1.43 | length 33
  Top Layer w0.152: U1.43@24.162,42.814 24.236,42.888 24.236,43.679 v2(24.669,44.112)
  Bottom Layer w0.152: v2(24.669,44.112) 24.669,49.697 27.603,52.631 33.186,52.631 36.575,56.02 36.577,56.018 40.808,56.018 43.41,58.621 J2.5@46.838,58.621
MCU_SCLK: J2.13 U1.61 U3.17 | length 50.4
  Top Layer w0.152: U3.17@25.72,64.253 32.706,64.253 34.341,62.618 34.341,61.161 34.341,60.072 34.341,55.729 29.449,50.838 28.686,50.838 U1.61@28.612,50.764 28.572,50.804 27.763,50.804 27.597,50.971 26.884,50.971 25.864,49.95 25.864,49.573 v2(25.827,49.537)
  Bottom Layer w0.152: v2(25.827,49.537) 25.827,48.978 27.542,47.264 40.562,47.264 41.759,48.461 J2.13@46.838,48.461
MCU_SDI: J2.9 U1.60 U3.18 | length 48
  Top Layer w0.152: U3.18@25.72,64.753 32.913,64.753 34.803,62.863 34.803,55.258 29.882,50.338 28.686,50.338 U1.60@28.612,50.264 28.598,50.249 27.278,50.249 v2(27.263,50.235)
  Bottom Layer w0.152: v2(27.263,50.235) 27.592,50.563 36.708,50.563 39.685,53.541 J2.9@46.838,53.541
MCU_SDO: J2.11 U1.59 U3.19 | length 50.7
  Top Layer w0.152: U3.19@25.72,65.253 33.12,65.253 35.341,63.032 35.341,61.161 35.155,60.975 35.155,54.569 30.424,49.838 28.686,49.838 U1.59@28.612,49.764 28.538,49.69 27.737,49.69 27.583,49.537 27.155,49.537 v2(27.067,49.449)
  Bottom Layer w0.152: v2(27.067,49.449) 28.285,48.232 38.285,48.232 41.054,51.001 J2.11@46.838,51.001
MCU_SO: J2.17 U1.9 | length 42.3
  Top Layer w0.152: v2(22.583,55.577) 22.622,55.538 22.622,54.254 U1.9@22.662,54.214
  Bottom Layer w0.152: v2(22.583,55.577) 22.583,55.454 22.279,55.15 22.279,41.355 23.645,39.988 40.903,39.988 44.295,43.381 J2.17@46.838,43.381
MCU_STATUS: D2.2 U1.26 | length 10.1
  Top Layer w0.152: D2.2@8.345,44.812 13.546,44.812 16.424,47.69 17.138,47.69 U1.26@17.212,47.764
NetC2_1: C2.1 IC1.1 R6.2 USB1.6 USB1.7 USB1.8 USB1.9 USB1.10 USB1.11 | length 28.8
  Top Layer w0.203: v3(6.416,14.01) 6.358,13.951 6.358,13.463 6.874,12.946 7.158,12.946 7.356,12.748 R6.2@7.356,12.648 7.356,12.602 7.555,12.403 C2.1@8.626,12.403 ; IC1.1@8.128,19.726 8.14,19.726 8.141,19.724 8.141,18.673 v3(8.154,18.66)
  Top Layer w0.254: USB1.10@1.37,16.595 1.589,16.814 2.507,16.814 2.829,17.136 2.829,17.472 USB1.11@3.456,18.099 ; USB1.7@1.524,24.48 2.873,24.48 4.061,23.293 USB1.6@4.061,23.229 ; USB1.11@3.67,18.083 3.456,18.083 2.88,18.659 2.458,18.659 2.193,18.924 2.193,19.047 1.648,19.593 1.524,19.593 1.524,21.468 2.084,22.028 2.547,22.028 3.512,22.993 USB1.6@3.824,22.993 ; USB1.11@3.824,18.068 4.116,18.068 4.726,17.457 4.726,17.182 5.244,16.663 5.244,15.182 v3(6.416,14.01)
  Bottom Layer w0.254: v3(6.416,14.01) 6.416,15.278 8.154,17.016 v3(8.154,18.66)
NetC11_1: C11.1 R13.2 XDS1.96 | length 5.5
  Top Layer w0.203: R13.2@13.401,10.174 13.44,10.135 C11.1@14.88,10.135 14.88,10.235 15.56,10.916 XDS1.96@15.56,13.883
NetC12_1: C12.1 R14.1 R16.2 XDS1.70 | length 10
  Top Layer w0.203: R14.1@12.929,29.535 12.941,29.522 14.477,29.522 R16.2@14.49,29.509 ; 13.769,29.482 13.769,28.019 16.006,28.019 16.561,27.463 16.561,24.534 16.308,24.28 XDS1.70@15.607,24.28
NetC15_1: C15.1 C16.1 C17.1 XDS1.87 XDS1.115 | length 17.8
  Top Layer w0.203: XDS1.87@15.619,17.488 16.78,17.49 ; C15.1@22.919,10.149 C16.1@24.452,10.149 ; 24.307,14.467 24.307,14.465 24.755,14.017 24.755,13.596 24.309,13.15 24.309,12.382 XDS1.115@24.307,12.38 24.307,11.198 24.452,11.053 C16.1@24.452,10.149 ; C17.1@25.985,10.149 C16.1@24.452,10.149
  Top Layer w0.508: 16.78,17.49 21.285,17.49 24.307,14.467
NetC18_1: C18.1 XDS1.88 Y1.3 | length 6.4
  Top Layer w0.203: C18.1@11.753,19.488 11.753,18.535 11.307,18.089 11.307,17.939 11.806,17.44 12.013,17.233 12.013,17.224 12.157,17.08 XDS1.88@15.607,17.08
NetC19_1: C19.1 XDS1.89 Y1.1 | length 5
  Top Layer w0.203: C19.1@12.879,14.042 12.953,14.116 12.953,15.843 12.907,15.889 12.907,15.989 13.606,16.688 XDS1.89@15.619,16.688
NetC20_1: C20.1 C21.1 IC3.3 R17.1 XDS1.9 | length 8.3
  Top Layer w0.203: XDS1.9@31.019,17.088 31.021,17.09 31.721,17.09 32.489,17.858 32.489,18.162 33.456,19.128 R17.1@33.556,19.128 C20.1@33.556,20.651 C21.1@33.556,22.174 33.556,22.967 33.618,23.029 33.618,23.574 33.717,23.672 IC3.3@33.892,23.672
NetC22_1: C22.1 R18.1 XDS1.68 | length 3.4
  Top Layer w0.203: R18.1@13.529,23.27 C22.1@13.529,24.78 ; C22.1@13.825,24.976 13.827,24.978 14.097,24.978 14.206,25.088 XDS1.68@15.619,25.088
NetC25_2: C25.2 U1.32 | length 2.3
  Top Layer w0.152: C25.2@15.558,43.688 16.101,44.231 16.101,44.492 16.299,44.69 17.138,44.69 U1.32@17.212,44.764
NetC58_2: C58.2 D11.1 J9.1 Q7.1 Q7.2 Q7.3 R45.1 TP37.1 | length 44.2
  Top Layer w0.152: Q7.1@80.101,22.697 79.479,22.076 72.418,22.076 67.271,27.223 67.271,34.123 68.426,35.278 71.027,35.278 75.078,39.329 83.107,39.329 84.169,40.391 84.169,40.506 84.625,40.506 R45.1@84.694,40.437
  Top Layer w0.7: C58.2@79.477,14.453 C58.2@79.502,14.453 ; D11.1@81.342,15.484 81.737,15.878 83.113,15.878
NetC82_2: C82.2 R69.1 R70.2
NetD1_1: D1.1 R28.2 | length 2.4
  Top Layer w0.152: R28.2@4.305,39.921 D1.1@6.745,39.921
NetD2_1: D2.1 R29.2 | length 2.6
  Top Layer w0.152: R29.2@4.277,44.582 4.507,44.812 D2.1@6.745,44.812
NetD3_1: D3.1 R30.2 | length 2.7
  Top Layer w0.152: R30.2@4.042,37.724 D3.1@6.745,37.724
NetD4_1: D4.1 R31.2 | length 2.6
  Top Layer w0.152: R31.2@4.252,42.296 4.466,42.511 D4.1@6.745,42.511
NetD5_1: D5.1 F1.1 Q4.1 Q4.2 Q4.3
NetD5_2: D5.2 Q1.2
NetD6_1: D6.1 R62.2 | length 3.3
  Top Layer w0.381: R62.2@44.368,80.711 44.394,80.685 44.394,77.473 D6.1@44.42,77.447
NetD7_1: D7.1 R63.2 | length 3.2
  Top Layer w0.381: R63.2@40.566,80.661 40.585,80.642 D7.1@40.585,77.466
NetD10_1: D10.1 R44.2 | length 3.2
  Top Layer w0.254: R44.2@118.016,46.438 118.016,45.682 D10.1@119.748,43.951
NetJ3_2: J3.2 R24.1 | length 2.4
  Top Layer w0.152: R24.1@1.927,52.264 1.955,52.236 J3.2@1.955,49.834
NetJ20_1: J20.1 R67.1 | length 7.7
  Top Layer w0.152: v2(36.459,67.373) 36.459,68.284 R67.1@36.575,68.4
  Bottom Layer w0.152: J20.1@32.026,62.555 36.371,66.901 36.371,67.286 v2(36.459,67.373)
NetJ23_2: J23.2 Q8.5 Q8.6 Q8.7 Q8.8 Q8.9@70.18,31.404
NetLED1_1: LED1.1 R19.1 | length 29.4
  Top Layer w0.203: v3(7.813,11.19) 7.832,11.19 8.073,10.949 LED1.1@8.753,10.949 ; v3(32.724,10.434) R19.1@33.59,10.434
  Bottom Layer w0.203: v3(7.813,11.19) 8.321,11.698 12.262,11.698 13.888,10.073 27.803,10.073 29.988,12.257 30.901,12.257 v3(32.724,10.434)
NetLED2_1: LED2.1 R20.1 | length 22.6
  Top Layer w0.203: v3(9.769,10.835) 10.721,10.835 LED2.1@10.785,10.899 ; v3(29.632,10.428) 29.635,10.431 30.423,10.431 R20.1@30.426,10.434
  Bottom Layer w0.203: v3(9.769,10.835) 10.328,10.276 12.766,10.276 13.452,9.59 28.794,9.59 v3(29.632,10.428)
NetQ1_1: Q1.1 R33.2
NetQ1_3: Q1.3 Q4.4 R32.2
NetQ2_4: Q2.4 R34.1 TP23.1 | length 7.2
  Top Layer w0.152: Q2.4@89.798,34.639 89.798,35.513 TP23.1@87.546,37.765 89.32,39.538 89.569,39.538 R34.1@89.859,39.828
NetQ3_4: Q3.4 R35.1 TP22.1 | length 11.2
  Top Layer w0.152: R35.1@108.325,40.648 109.539,39.435 TP22.1@109.539,37.765 109.539,35.776 110.036,35.279 110.036,31.967 109.641,31.571 109.641,31.16 109.403,30.922 109.312,30.922 Q3.4@109.234,30.845 ; TP22.1@108.965,37.715 TP22.1@109.161,37.911
NetQ5_4: Q5.4 R39.1 TP29.1 | length 6.7
  Top Layer w0.152: Q5.4@96.71,34.639 96.535,34.639 95.795,35.379 TP29.1@95.795,37.765 96.189,38.159 96.189,38.922 96.969,39.702 97.408,39.702 R39.1@97.583,39.877
NetQ6_4: Q6.4 R40.1 TP28.1 | length 10.7
  Top Layer w0.152: R40.1@101.773,39.783 103.833,37.723 103.833,37.457 103.287,36.912 103.287,31.45 102.847,31.009 102.432,31.009 Q6.4@102.267,30.845
NetQ7_4: Q7.4 R47.1 TP34.1 | length 40.8
  Top Layer w0.152: TP34.1@79.119,37.765 78.888,37.996 77.118,37.996 76.434,37.312 74.162,37.312 71.586,34.737 68.316,34.737 67.61,34.031 67.61,27.933 72.115,23.428 83.379,23.428 83.911,22.897 Q7.4@83.911,22.697 ; TP34.1@79.164,37.952 80.506,37.952 80.887,38.333 R47.1@81.92,38.333
NetQ8_4: Q8.4 R51.2 TP39.1 | length 14.7
  Top Layer w0.152: Q8.4@66.28,29.499 v6(66.28,28.208) 66.28,26.759 66.312,26.728 66.312,25.692 R51.2@66.391,25.612
  Bottom Layer w0.152: v6(66.28,28.208) 69.463,31.391 TP39.1@69.463,37.608
NetR2_1: R2.1 USB1.5 | length 6.3
  Top Layer w0.406: USB1.5@3.837,21.83 5.171,21.83 6.772,23.431 6.772,25.241 6.414,25.599 6.389,25.599 6.117,25.871 R2.1@6.117,25.896
NetR5_1: R5.1 USB1.1 | length 3.6
  Top Layer w0.406: USB1.1@3.898,19.23 5.87,19.23 6.385,18.715 6.385,18.085 R5.1@6.582,17.888
NetR9_1: R9.1 XDS1.63 | length 20.8
  Top Layer w0.203: v3(17.084,25.592) 17.084,26.481 17.507,26.904 XDS1.63@17.507,27.182 ; v3(33.798,27.624) 33.856,27.682 33.964,27.682 34.668,28.386 R9.1@34.768,28.386
  Bottom Layer w0.203: v3(17.084,25.592) 17.912,25.592 18.141,25.364 31.537,25.364 v3(33.798,27.624)
NetR10_1: R10.1 XDS1.62 | length 23.5
  Top Layer w0.203: v3(17.313,24.805) 17.356,24.848 17.356,25.146 17.592,25.382 17.592,26.38 17.906,26.693 XDS1.62@17.906,27.182 ; v3(34.534,29.224) 34.534,29.72 34.733,29.919 R10.1@34.768,29.919
  Bottom Layer w0.203: v3(17.313,24.805) 17.364,24.754 31.715,24.754 34.534,27.573 v3(34.534,29.224)
NetR11_1: R11.1 XDS1.61 | length 26.4
  Top Layer w0.203: v3(18.05,23.89) 17.999,23.941 17.999,26.283 18.306,26.59 XDS1.61@18.306,27.182 ; R11.1@34.768,31.452 34.868,31.452 35.066,31.253 35.066,30.8 v3(35.093,30.774)
  Bottom Layer w0.203: v3(18.05,23.89) 18.05,23.857 18.321,23.586 31.207,23.586 35.093,27.472 v3(35.093,30.774)
NetR12_1: R12.1 XDS1.60 | length 7.1
  Top Layer w0.203: R12.1@13.825,26.422 13.925,26.422 14.417,26.915 16.015,26.915 v3(16.018,26.913) ; v3(18.507,26.024) 18.507,26.106 18.707,26.307 XDS1.60@18.707,27.78
  Bottom Layer w0.203: v3(16.018,26.913) 16.491,26.439 16.956,26.439 17.371,26.024 v3(18.507,26.024)
NetR15_2: R15.2 XDS1.59 | length 2.2
  Top Layer w0.203: R15.2@18.119,29.482 18.219,29.482 19.117,28.583 XDS1.59@19.117,27.79
NetR19_2: R19.2 XDS1.3 | length 7.3
  Top Layer w0.203: XDS1.3@30.409,14.68 30.307,14.68 29.988,14.361 29.988,13.756 32.321,11.422 33.701,11.422 34.69,10.434 R19.2@34.79,10.434
NetR20_2: R20.2 XDS1.4 | length 6.7
  Top Layer w0.203: XDS1.4@31.017,15.086 29.972,15.086 29.607,14.721 29.607,13.578 31.626,11.559 R20.2@31.626,10.434
nFAULT: R31.1 U1.27 | length 16.5
  Top Layer w0.152: R31.1@2.228,42.695 R31.1@2.228,42.719 ; R31.1@2.627,42.296 R31.1@2.652,42.296 2.677,42.296 4.211,43.83 13.779,43.83 16.234,46.285 16.234,46.98 16.396,47.143 16.449,47.143 16.491,47.143 U1.27@16.612,47.264
nSCS_DRV: J2.8 TP12.1 U2.16 | length 50.1
  Top Layer w0.152: TP12.1@54.958,55.472 55.332,55.846 55.332,56.679 60.427,61.773 68.94,61.773 81.344,49.369 90.602,49.369 90.633,49.338 90.866,49.338 U2.16@90.915,49.289
  Bottom Layer w0.152: J2.8@49.378,56.081 49.641,55.817 54.613,55.817 TP12.1@54.958,55.472
nSLEEP: J2.22 TP19.1 U2.23 | length 47.7
  Top Layer w0.152: J2.22@49.378,38.301 51.918,35.761 TP19.1@54.958,35.761 62.173,35.761 69.788,43.376 74.732,43.376 76.05,44.693 82.759,44.693 83.488,43.964 v1@83.529,43.964 ; v1(88.622,44.298) 89.303,44.979 89.601,44.979 90.362,45.74 90.866,45.74 U2.23@90.915,45.789
  Bottom Layer w0.152: TP19.1@55.212,35.761 TP19.1@55.212,36.039 ; v1(83.479,43.973) 86.832,43.973 87.157,44.298 v1(88.622,44.298)
NU/LIN: C80.1 D9.1 J18.1 J19.3 J21.8 U3.31 | length 38.7
  Top Layer w0.254: v2(17.552,84.367) 17.484,84.299 17.484,82.704 J18.1@16.972,82.192 17.022,82.142 J19.3@17.022,78.921 17.022,75.977 D9.1@17.052,75.947 17.052,74.002 C80.1@17.996,73.058 ; C80.1@17.988,72.859 17.988,72.669 18.115,72.542 18.289,72.542 22.022,68.809 22.022,68.622 U3.31@22.068,68.576 ; v2(24.623,93.846) 24.623,93.942 24.835,94.154 J21.8@24.835,99.033
  Bottom Layer w0.254: v2(17.552,84.367) 18.458,85.273 18.458,92.789 19.515,93.846 v2(24.623,93.846)
OUT1: C49.2 C50.2 J6.1 TP31.1 U2.11
OUT2: C52.2 C54.2 J6.2 TP32.1 U2.12 | length 0.2
  Top Layer w0.152: U2.12@91.565,51.439 U2.12@91.565,51.614
OUT3: C56.2 C61.2 J8.2 TP35.1 U2.48
  other v1: 98.417,50.874 99.103,50.874 99.787,50.874 100.398,51.097 100.869,51.495 101.281,51.98 101.815,52.416 102.345,52.908 101.448,53.122 102.856,53.455 102.017,53.655 103.369,53.99 102.615,54.235 103.129,54.767
OUT4: C51.2 C60.2 J7.1 TP38.1 U2.1
  other v1: 99.624,51.678 98.902,51.704 98.2,51.729 100.142,51.999 99.247,52.172 98.695,52.198 99.725,52.416 100.598,52.416
OUT5: C53.2 C55.2 J7.2 TP33.1 U2.9
OUT6: C57.2 C59.2 J8.1 TP36.1 U2.46
  other v1: 102.349,49.999 98.62,50.071 99.215,50.071 99.822,50.071 100.444,50.071 101.021,50.071 101.598,50.071 103.129,50.14 102.069,50.65 101.394,50.712 102.707,50.789 103.926,50.893 103.252,50.92 101.88,51.243 103.085,51.488 102.432,51.551 103.753,51.622 102.932,52.044 103.545,52.278 103.926,52.886
OUT7: C71.2 C90.2 J10.2 TP46.1 U2.44 | length 59.9
  Top Layer w0.254: U2.44@97.715,48.789 98.396,48.789 98.849,48.336 99.056,48.336 v1(99.103,48.289)
  Mid-Layer 2 w0.254: v1(99.103,48.289) 99.962,49.148 104.075,49.148 127.889,72.961 127.889,80.899 131.718,84.728 TP46.1@137.658,84.728
OUT8: C64.2 C87.2 J10.1 TP40.1 U2.43 | length 2
  Top Layer w0.254: U2.43@97.715,48.289 97.717,48.287 98.323,48.287 99.086,47.523 99.431,47.523
  other v1: 100.055,47.631 101.174,47.665 102.566,47.665
OUT9: C72.2 C91.2 J11.2 TP47.1 U2.42 | length 1.9
  Top Layer w0.254: U2.42@97.715,47.789 97.717,47.787 98.248,47.787 99.238,46.797
  other v1: 99.735,46.778 101.829,46.811 103.731,46.811
OUT10: C65.2 C88.2 J11.1 TP41.1 U2.41 | length 5.5
  Top Layer w0.254: U2.41@97.715,47.289 97.717,47.287 98.173,47.287 99.535,45.926 ; v1(102.432,46.012) 102.365,46.012 102.279,45.926 99.535,45.926 ; 99.535,45.926 99.61,45.851 99.607,45.851 99.532,45.926 99.535,45.926
  other v1: 100.169,45.926 104.43,45.926
OUT11: C73.2 C92.2 J12.2 J23.1 TP48.1 U2.40 | length 8.4
  Top Layer w0.254: U2.40@97.715,46.789 97.717,46.787 98.096,46.787 99.809,45.074 v1(100.776,45.074) 100.787,45.084 102.593,45.084 v1(102.604,45.095) 102.615,45.084 104.419,45.084 v1(104.43,45.074) 105.353,45.074
OUT12: C66.2 C89.2 J12.1 TP42.1 U2.39 | length 5.1
  Top Layer w0.254: U2.39@97.715,46.289 97.717,46.287 98.021,46.287 100.321,43.987 v1@101.911,43.987
  other v1: 103.645,43.978 105.702,43.957 101.88,44.018
PI_IN: C33.1 C34.1 C35.1 C39.2 L1.1 Q4.5 Q4.6 Q4.7 Q4.8 Q4.9@123.011,40.548 R66.1 R75.1
PVDD: C30.2 C31.1 C32.2 C36.1 C37.1 C38.1 C44.1 C45.2 C46.2 D10.2 J23.3 L1.2 Q2.5 Q2.6 Q2.7 Q2.8 Q2.9@85.898,32.734 Q3.5 Q3.6 Q3.7 Q3.8 Q3.9@113.134,32.75 Q7.5 Q7.6 Q7.7 Q7.8 Q7.9@82.006,26.497 R64.2 R66.2 R75.2 R76.2 TP20.1 U2.2 U2.8 U2.45 | length 3
  Top Layer w0.152: U2.8@93.552,51.452 U2.8@93.565,51.439 ; C45.2@93.605,55.557 C45.2@93.616,55.546 ; U2.2@96.565,51.439 96.565,51.614 96.664,51.713 96.664,51.824 97.824,52.984 97.824,53.081 98.312,53.569 C46.2@98.409,53.569
  other v1: 115.789,21.488 116.5,21.488 119.345,21.488 111.166,22.2 111.877,22.2 112.588,22.2 113.3,22.2 114.011,22.2 114.722,22.2 115.433,22.2 116.144,22.2 119.7,22.2 110.81,22.911 111.522,22.911 112.233,22.911 112.944,22.911 113.655,22.911 114.366,22.911 115.078,22.911 115.789,22.911 116.5,22.911 111.166,23.622 111.877,23.622 112.588,23.622 113.3,23.622 114.011,23.622 114.722,23.622 115.433,23.622 116.144,23.622 116.856,23.622 118.989,23.622 119.7,23.622 110.81,24.333 111.522,24.333 112.233,24.333 112.944,24.333 113.655,24.333 114.366,24.333 115.078,24.333 115.789,24.333 116.5,24.333 117.211,24.333 117.922,24.333 118.634,24.333 119.345,24.333 74.895,25.044 75.606,25.044 76.317,25.044 77.028,25.044 77.74,25.044 78.451,25.044 79.162,25.044 84.852,25.044 85.563,25.044 86.274,25.044 86.985,25.044 87.696,25.044 111.166,25.044 111.877,25.044 112.588,25.044 113.3,25.044 114.011,25.044 114.722,25.044 115.433,25.044 116.144,25.044 116.856,25.044 117.567,25.044 118.278,25.044 118.989,25.044 119.7,25.044 75.25,25.756 75.962,25.756 76.673,25.756 77.384,25.756 78.095,25.756 78.806,25.756 85.207,25.756 85.918,25.756 86.63,25.756 87.341,25.756 88.052,25.756 110.81,25.756 111.522,25.756 112.233,25.756 112.944,25.756 113.655,25.756 114.366,25.756 115.078,25.756 115.789,25.756 116.5,25.756 117.211,25.756 117.922,25.756 118.634,25.756 119.345,25.756 74.184,26.467 74.895,26.467 75.606,26.467 76.317,26.467 77.028,26.467 77.74,26.467 78.451,26.467 79.162,26.467 84.852,26.467 85.563,26.467 86.274,26.467 86.985,26.467 87.696,26.467 111.166,26.467 111.877,26.467 112.588,26.467 113.3,26.467 114.011,26.467 114.722,26.467 115.433,26.467 116.144,26.467 73.828,27.178 74.539,27.178 75.25,27.178 75.962,27.178 76.673,27.178 77.384,27.178 78.095,27.178 78.806,27.178 85.207,27.178 85.918,27.178 86.63,27.178 87.341,27.178 88.052,27.178 110.81,27.178 111.522,27.178 112.233,27.178 112.944,27.178 113.655,27.178 114.366,27.178 115.078,27.178 115.789,27.178 116.5,27.178 74.184,27.889 74.895,27.889 75.606,27.889 76.317,27.889 77.028,27.889 77.74,27.889 78.451,27.889 79.162,27.889 84.852,27.889 85.563,27.889 86.274,27.889 86.985,27.889 87.696,27.889 111.166,27.889 111.877,27.889 112.588,27.889 113.3,27.889 114.011,27.889 114.722,27.889 115.433,27.889 116.144,27.889 73.828,28.6 74.539,28.6 75.25,28.6 75.962,28.6 76.673,28.6 77.384,28.6 78.095,28.6 78.806,28.6 85.207,28.6 85.918,28.6 86.63,28.6 87.341,28.6 88.052,28.6 110.81,28.6 111.522,28.6 112.233,28.6 112.944,28.6 113.655,28.6 114.366,28.6 115.078,28.6 115.789,28.6 116.5,28.6 75.606,29.312 76.317,29.312 77.028,29.312 77.74,29.312 78.451,29.312 79.162,29.312 79.873,29.312 80.584,29.312 81.296,29.312 82.007,29.312 82.718,29.312 83.429,29.312 84.14,29.312 84.852,29.312 85.563,29.312 86.274,29.312 86.985,29.312 87.696,29.312 111.166,29.312 111.877,29.312 112.588,29.312 113.3,29.312 114.011,29.312 114.722,29.312 115.433,29.312 116.144,29.312 75.962,30.023 76.673,30.023 77.384,30.023 78.095,30.023 78.806,30.023 79.518,30.023 80.229,30.023 80.94,30.023 81.651,30.023 82.362,30.023 83.074,30.023 115.789,30.023 116.5,30.023 75.606,30.734 76.317,30.734 77.028,30.734 77.74,30.734 78.451,30.734 79.162,30.734 79.873,30.734 80.584,30.734 81.296,30.734 82.007,30.734 82.718,30.734 116.144,30.734 78.095,31.445 78.806,31.445 79.518,31.445 80.229,31.445 80.94,31.445 81.651,31.445 82.362,31.445 83.074,31.445 115.789,31.445 116.5,31.445 78.451,32.156 79.162,32.156 79.873,32.156 80.584,32.156 81.296,32.156 82.007,32.156 82.718,32.156 116.144,32.156 78.095,32.868 78.806,32.868 79.518,32.868 80.229,32.868 80.94,32.868 115.789,32.868 116.5,32.868 78.451,33.579 79.162,33.579 79.873,33.579 80.584,33.579 116.144,33.579 115.789,34.29 116.5,34.29 116.144,35.001 115.789,35.712 116.5,35.712 117.789,36.36 118.5,36.36 119.211,36.36 119.828,36.375 114.011,36.424 114.722,36.424 116.856,36.424 118.145,37.072 118.856,37.072 119.567,37.072 114.366,37.135 117.211,37.135 19.236,59.889 20.323,59.889 94.871,60.337 95.705,60.337 96.594,60.337 94.871,61.443 95.705,61.443 96.594,61.443
PVDD_ADC: R76.1 R77.2 U1.10 | length 5.6
  Top Layer w0.152: U1.10@22.162,54.214 22.162,55.243 22.049,55.356 22.049,55.682 21.315,56.416 R76.1@21.315,57.4 21.457,57.258 R77.2@23.36,57.258
PWM1: J2.6 TP11.1 U2.15 | length 49.3
  Top Layer w0.152: TP11.1@54.958,59.282 59.253,63.576 69.469,63.576 82.756,50.289 85.522,50.289 86.022,49.789 U2.15@90.915,49.789
  Bottom Layer w0.152: J2.6@49.378,58.621 53.74,58.621 54.401,59.282 TP11.1@54.958,59.282
REF_TARGET_VCC: XDS1.120
RST: C26.2 J1.10 R25.1 S1.1 S1.2 U1.38 | length 71.8
  Top Layer w0.152: C26.2@8.98,47.764 9.72,48.504 9.72,48.94 S1.2@10.344,49.564 S1.1@10.344,56.564 10.344,56.78 9.72,57.403 9.504,57.403 8.798,58.11 R25.1@8.798,59.055 4.838,59.055 1.092,55.309 1.092,37.249 5.112,33.229 19.48,33.229 20.581,34.33 J1.10@20.818,34.33 19.177,35.971 19.177,39.583 21.382,41.788 21.398,41.788 21.588,41.979 21.588,41.994 21.59,41.996 21.59,42.518 U1.38@21.662,42.59
S_N: C62.2 R58.1 TP45.1 U2.30 | length 62.7
  Top Layer w0.152: v6(89.932,21.59) 91.351,21.59 R58.1@91.374,21.614 ; TP45.1@93.545,41.403 93.565,41.423 C62.2@93.565,43.059 93.565,43.535 94.065,44.035 U2.30@94.065,44.639
  Bottom Layer w0.152: v6(89.932,21.59) 72.904,21.59 70.304,24.19 70.304,35.582 75.681,40.959 93.101,40.959 TP45.1@93.545,41.403
S_P: C62.1 R52.1 TP43.1 U2.31 | length 61.7
  Top Layer w0.152: v2(89.896,22.917) 89.933,22.954 90.985,22.954 R52.1@91.384,23.353 ; U2.31@94.565,44.639 94.565,44.035 95.065,43.535 C62.1@95.065,43.059 95.065,41.452 TP43.1@95.114,41.403
  Bottom Layer w0.152: v2(89.896,22.917) 89.812,22.917 89.578,22.684 81.805,22.684 81.793,22.695 73.301,22.695 71.323,24.673 71.323,35.478 76.26,40.415 94.126,40.415 TP43.1@95.114,41.403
